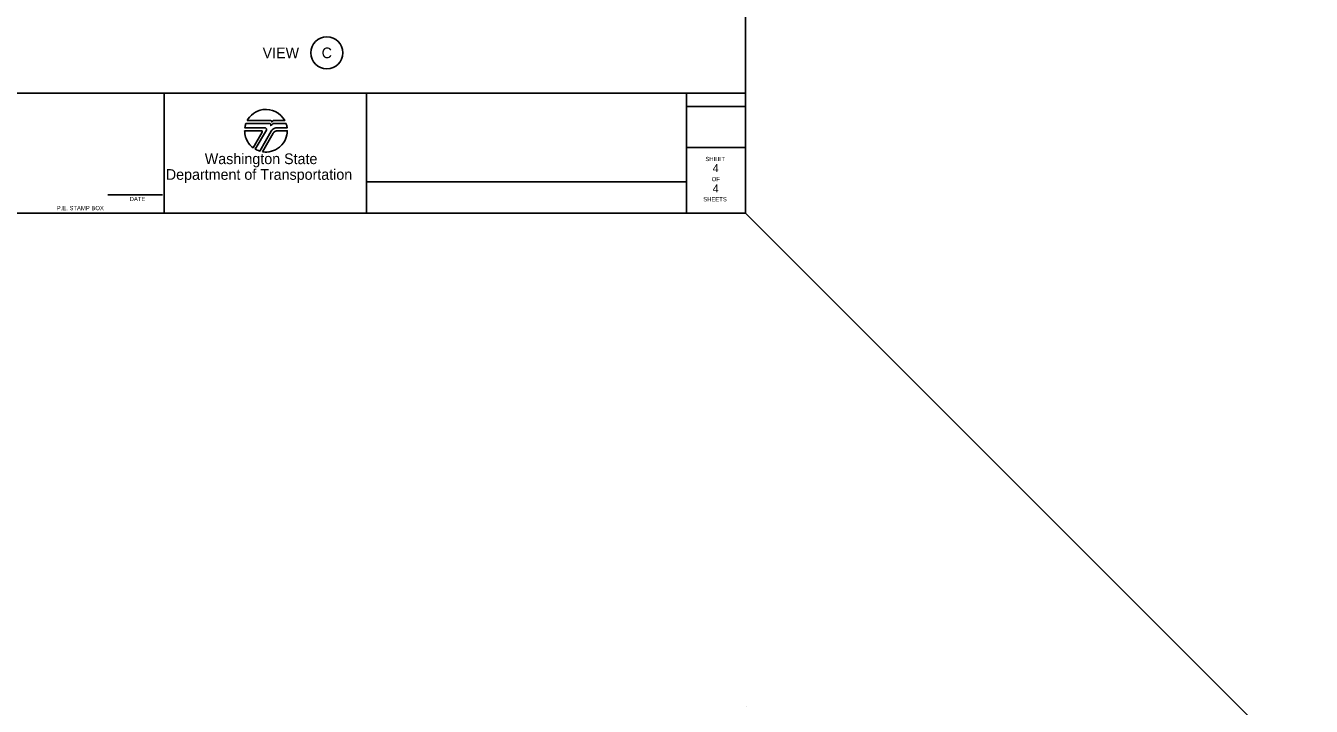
# Model space of a CAD drawing. Extents: x 99862 to 104211, y 98939 to 111076.
# Drawn here: x 101800 to 104211, y 108075 to 109352 of the extents above; entities that cross this region are included whole.
import ezdxf

# ---------------------------------------------------------------- set-up
doc = ezdxf.new("R2010")
doc.units = 0
for name, color, linetype in [('Level 1', 7, 'Continuous'), ('Level 20', 7, 'Continuous'), ('Level 60', 7, 'Continuous'), ('SH_GI_SheetLocationText', 7, 'Continuous')]:
    doc.layers.add(name, color=color, linetype=linetype)

msp = doc.modelspace()

# ---------------------------------------------------------------- linework, layer by layer
at = {"layer": 'Level 1'}
msp.add_line((103150, 109000), (104210.7, 107939.3), dxfattribs=at)
at = {"layer": 'Level 20'}
msp.add_circle((102365, 109301), 30, dxfattribs=at)
at = {"layer": 'Level 60'}
for p, q in [((103150, 109000), (103150, 111075)), ((100000, 109225), (103150, 109225)), ((102060.1, 109225), (102060.1, 109000)), ((102439.1, 109225), (102439.1, 109000)), ((103039.1, 109225), (103039.1, 109000)), ((103039.1, 109200), (103150, 109200)), ((103039.1, 109123.4), (103150, 109123.4)), ((102439.1, 109059.1), (103039.1, 109059.1)), ((101954.4, 109034.6), (102056.6, 109034.6)), ((100000, 109000), (103150, 109000)), ((103151, 108075.5), (103151, 108075.5))]:
    msp.add_line(p, q, dxfattribs=at)
for points in [[(102215.6, 109173.9), (102259.9, 109173.9), (102260.7, 109173.7), (102261.4, 109173.2), (102261.7, 109172.6), (102261.7, 109172), (102261.5, 109171.2), (102262.3, 109172.2), (102263.5, 109173.1), (102265.2, 109173.8), (102266.4, 109173.9), (102285.9, 109173.9), (102283, 109178.5), (102278.9, 109183.3), (102273.7, 109187.6), (102268.3, 109190.8), (102263.3, 109192.8), (102257.6, 109194.2), (102251.6, 109194.8), (102245.1, 109194.4), (102239.7, 109193.3), (102235.1, 109191.6), (102231.1, 109189.6), (102227.3, 109187.2), (102223.7, 109184.3), (102219.8, 109180.1), (102217.5, 109176.9)], [(102215.6, 109173.9), (102259.9, 109173.9), (102260.7, 109173.7), (102261.4, 109173.2), (102261.7, 109172.6), (102261.7, 109172), (102261.5, 109171.2), (102262.3, 109172.2), (102263.5, 109173.1), (102265.2, 109173.8), (102266.4, 109173.9), (102285.9, 109173.9), (102283, 109178.5), (102278.9, 109183.3), (102273.7, 109187.6), (102268.3, 109190.8), (102263.3, 109192.8), (102257.6, 109194.2), (102251.6, 109194.8), (102245.1, 109194.4), (102239.7, 109193.3), (102235.1, 109191.6), (102231.1, 109189.6), (102227.3, 109187.2), (102223.7, 109184.3), (102219.8, 109180.1), (102217.5, 109176.9)], [(102213.3, 109168.7), (102257.2, 109168.7), (102257.9, 109168.6), (102258.5, 109168.4), (102258.9, 109168.2), (102259.2, 109167.9), (102259.7, 109167.3), (102260, 109166.6), (102260.2, 109165.9), (102260.1, 109165.2), (102260, 109164.7), (102259.7, 109164.2), (102260.2, 109164.9), (102261.1, 109165.9), (102262.1, 109166.8), (102263.4, 109167.6), (102264.6, 109168.1), (102266.5, 109168.6), (102269.2, 109168.7), (102288.3, 109168.7), (102289.1, 109166.2), (102289.6, 109164.5), (102290, 109162.7), (102290.3, 109160.9), (102290.4, 109160.1), (102272, 109160.1), (102269.5, 109160), (102267.7, 109159.7), (102265.2, 109158.7), (102263.2, 109157.2), (102261.8, 109155.7), (102260.6, 109153.7), (102239.1, 109116.6), (102236.5, 109117.5), (102234.2, 109118.5), (102232.2, 109119.5), (102230.7, 109120.3), (102251.5, 109156.1), (102251.9, 109157.4), (102251.6, 109158.6), (102250.7, 109159.6), (102249.9, 109160), (102249.3, 109160.1), (102211.2, 109160.1), (102211.6, 109162.6), (102211.8, 109163.9), (102212.2, 109165.3), (102212.7, 109167)], [(102210.8, 109154.8), (102242.3, 109154.8), (102242.7, 109154.8), (102243.2, 109154.6), (102243.5, 109154.4), (102243.7, 109154.1), (102243.9, 109153.7), (102243.9, 109153.3), (102243.9, 109152.9), (102243.7, 109152.4), (102226.6, 109123), (102224.5, 109124.7), (102222.6, 109126.5), (102220.7, 109128.5), (102218.3, 109131.5), (102216.6, 109134.1), (102215, 109137), (102213.6, 109140.2), (102212.6, 109143), (102211.8, 109146), (102211.2, 109149), (102210.9, 109152)], [(102244.2, 109115.4), (102264.2, 109150), (102264.8, 109150.9), (102265.4, 109151.6), (102266.3, 109152.5), (102267.2, 109153.2), (102268.3, 109153.8), (102269.5, 109154.3), (102270.8, 109154.6), (102271.5, 109154.7), (102272.4, 109154.7), (102290.8, 109154.7), (102290.5, 109150.3), (102290, 109146.9), (102288.8, 109142.5), (102287.6, 109139.3), (102286, 109135.9), (102283.5, 109131.9), (102280.8, 109128.4), (102278.9, 109126.4), (102276.1, 109123.9), (102272.7, 109121.4), (102268.7, 109119.1), (102265, 109117.5), (102260.9, 109116.2), (102256.9, 109115.3), (102252.4, 109114.9), (102249.2, 109114.9), (102246.3, 109115.1)]]:
    msp.add_lwpolyline(points, close=True, dxfattribs=at)

# ---------------------------------------------------------------- texts
at = {"layer": 'Level 20'}
for s, p in [('VIEW', (102244.5, 109290.9)), ('C', (102355.2, 109290.9))]:
    msp.add_text(s, height=20, dxfattribs=at).set_placement(p)
at = {"layer": 'Level 60'}
for s, height, p in [('Washington State', 19.999, (102136.1, 109092.2)), ('SHEET', 8, (103074.6, 109097.8)), ('Department of Transportation', 19.999, (102063.1, 109062.8)), ('OF', 8, (103086.6, 109060.1)), ('DATE', 8.03, (101995.1, 109022.8)), ('SHEETS', 8, (103070.6, 109022.4)), ('P.E. STAMP BOX', 8, (101858.4, 109005.7))]:
    msp.add_text(s, height=height, dxfattribs=at).set_placement(p)
at = {"layer": 'SH_GI_SheetLocationText'}
for p in [(103088.4, 109077.2), (103088.4, 109039)]:
    msp.add_text('4', height=15, dxfattribs=at).set_placement(p)

doc.saveas('drawing.dxf')
